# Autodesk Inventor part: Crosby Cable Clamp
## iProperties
Title: Crosby Cable Clamp
Author: QBZ
Shininess: 60.0
PropertySet Name: _Private Model Information
Created: 2001-03
Part Number: Cable Clamp
Document SubType Name: Modeling
Designer: QBZ
Material: Steel, Mild
Catalog Web Link: http://www.thecrosbygroup.com
Description: 1/2 Cable Clamp
Vendor: Crosby
Control State: 0
Master: False
Checked Out: False
PropertySet Name: Design Tracking Control
Density: 7.860000000000001
Volumn: 33.57754930985285
Area: 110.20348715956722
PropertySet Name: Model Information
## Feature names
1. Extrusion1
2. Extrusion2
3. Extrusion3
4. Hole1
5. TaperEdge1
6. Fillet1
7. Sweep1
8. Chamfer1
